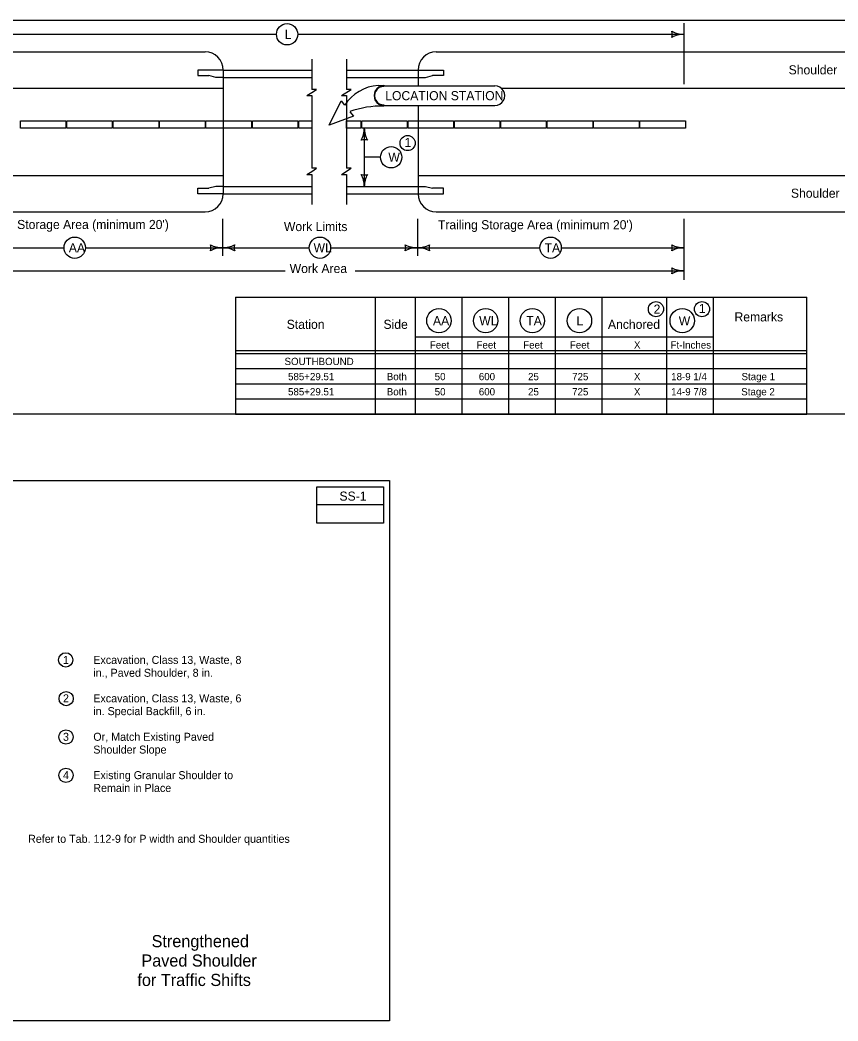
# Model space of a CAD drawing. Extents: x 8045 to 81668, y 6217 to 16762.
# Drawn here: x 8986 to 10335, y 10467 to 12118 of the extents above; entities that cross this region are included whole.
import ezdxf

# ---------------------------------------------------------------- set-up
doc = ezdxf.new("R2010")
doc.units = 0
for name, color, linetype in [('dsnNonPlotable', 7, 'Continuous'), ('dsnStdBlockModified', 7, 'Continuous'), ('dsnStdBlockNotModified', 7, 'Continuous'), ('dsnStdBorder', 7, 'Continuous'), ('dsnStdLineWork', 7, 'Continuous'), ('dsnStdNameDate', 7, 'Continuous'), ('Level 2', 7, 'Continuous'), ('Level 5', 7, 'Continuous')]:
    doc.layers.add(name, color=color, linetype=linetype)

msp = doc.modelspace()

# ---------------------------------------------------------------- linework, layer by layer
at = {"layer": 'dsnNonPlotable'}
for p, q in [((10080.5, 12113.1), (10080.5, 12012.3)), ((8530, 12094.5), (9408.5, 12094.5)), ((9443.8, 12094.5), (10080.5, 12094.5)), ((8162.3, 12065.5), (9290.8, 12065.5)), ((9672.2, 12065.5), (11020.7, 12065.5)), ((9466.8, 12053.5), (9466.8, 12003.7)), ((9523.9, 12053.5), (9523.9, 12003.7)), ((9320.8, 12035.5), (9278.8, 12035.5)), ((9278.8, 12035.5), (9278.8, 12026.5)), ((9278.8, 12026.5), (9296.8, 12026.5)), ((9308.8, 12023.5), (9296.8, 12026.5)), ((9320.8, 12023.5), (9308.8, 12023.5)), ((9320.8, 12035.5), (9320.8, 11831.5)), ((9320.8, 12035.5), (9466.8, 12035.5)), ((9320.8, 12023.5), (9466.8, 12023.5)), ((9523.9, 12035.5), (9642.2, 12035.5)), ((9523.9, 12023.5), (9642.2, 12023.5)), ((9642.2, 12035.5), (9684.2, 12035.5)), ((9642.2, 12035.5), (9642.2, 12009.5)), ((9642.2, 12023.5), (9654.2, 12023.5)), ((9654.2, 12023.5), (9666.2, 12026.5)), ((9684.2, 12026.5), (9666.2, 12026.5)), ((9684.2, 12035.5), (9684.2, 12026.5)), ((8078.7, 12005.5), (9320.8, 12005.5)), ((9576.3, 12010.1), (9585.8, 12010.4)), ((9585.8, 12010.4), (9585.8, 12008.6)), ((9585.8, 12009.5), (9769, 12009.5)), ((9779.7, 12005.5), (11111, 12005.5)), ((9458.8, 11993.6), (9466.8, 11998.6)), ((9458.8, 11993.6), (9466.8, 11993.6)), ((9466.8, 11998.6), (9474.8, 12003.7)), ((9474.8, 12003.7), (9466.8, 12003.7)), ((9466.8, 11993.6), (9466.8, 11933.5)), ((9515.9, 11993.6), (9531.9, 12003.7)), ((9515.9, 11993.6), (9523.9, 11993.6)), ((9531.9, 12003.7), (9523.9, 12003.7)), ((9523.9, 11993.6), (9523.9, 11933.5)), ((9495.4, 11944.5), (9515.5, 11984.5)), ((9515.5, 11984.5), (9521.1, 11977.5)), ((9585.8, 11977.9), (9585.8, 11976.1)), ((9585.8, 11977), (9769, 11977)), ((9642.2, 11977), (9642.2, 11831.5)), ((9535.6, 11959.5), (9495.4, 11944.5)), ((9529.7, 11966.8), (9535.6, 11959.5)), ((9553.5, 11939.8), (9553.5, 11843.5)), ((9466.8, 11933.5), (9466.8, 11873.5)), ((9523.9, 11933.5), (9523.9, 11873.5)), ((9580.1, 11891.7), (9553.5, 11891.7)), ((9466.8, 11868.4), (9474.8, 11873.5)), ((9474.8, 11873.5), (9466.8, 11873.5)), ((9515.9, 11863.4), (9531.9, 11873.5)), ((9531.9, 11873.5), (9523.9, 11873.5)), ((8078.7, 11861.5), (9320.8, 11861.5)), ((9458.8, 11863.4), (9466.8, 11868.4)), ((9458.8, 11863.4), (9466.8, 11863.4)), ((9466.8, 11863.4), (9466.8, 11813.5)), ((9515.9, 11863.4), (9523.9, 11863.4)), ((9523.9, 11863.4), (9523.9, 11813.5)), ((9642.2, 11861.5), (11111, 11861.5)), ((9278.8, 11840.5), (9296.8, 11840.5)), ((9278.8, 11831.5), (9278.8, 11840.5)), ((9308.8, 11843.5), (9296.8, 11840.5)), ((9320.8, 11843.5), (9308.8, 11843.5)), ((9320.8, 11843.5), (9466.8, 11843.5)), ((9523.9, 11843.5), (9642.2, 11843.5)), ((9642.2, 11843.5), (9654.2, 11843.5)), ((9654.2, 11843.5), (9666.2, 11840.5)), ((9684.2, 11840.5), (9666.2, 11840.5)), ((9684.2, 11831.5), (9684.2, 11840.5)), ((9320.8, 11831.5), (9278.8, 11831.5)), ((9320.8, 11831.5), (9466.8, 11831.5)), ((9523.9, 11831.5), (9642.2, 11831.5)), ((9642.2, 11831.5), (9684.2, 11831.5)), ((8162.3, 11801.5), (9290.8, 11801.5)), ((9319.6, 11790.2), (9319.6, 11729)), ((9641, 11790.2), (9641, 11729)), ((9672.2, 11801.5), (11020.7, 11801.5)), ((10080.5, 11790.2), (10080.5, 11689.4)), ((8832.1, 11742.4), (9058.2, 11742.4)), ((9093.5, 11742.4), (9319.6, 11742.4)), ((9319.6, 11742.4), (9462.8, 11742.4)), ((9497.8, 11742.4), (9641, 11742.4)), ((9510.5, 11742.4), (9641, 11742.4)), ((9641, 11742.4), (9843.1, 11742.4)), ((9878.4, 11742.4), (10080.5, 11742.4)), ((8832.1, 11704.5), (9422.9, 11704.5)), ((9538.2, 11704.5), (10080.5, 11704.5)), ((9539.6, 11704.5), (9641, 11704.5)), ((9572.1, 11468.1), (9572.1, 11661.1)), ((9638.1, 11468.1), (9638.1, 11661.1)), ((9715.1, 11468.1), (9715.1, 11661.1)), ((9792.1, 11468.1), (9792.1, 11661.1)), ((9869.1, 11468.1), (9869.1, 11661.1)), ((9638.1, 11595.3), (10129.7, 11595.3)), ((9341.1, 11573.1), (10283.7, 11573.1)), ((9341.1, 11568.1), (10283.7, 11568.1))]:
    msp.add_line(p, q, dxfattribs=at)
for points in [[(8986.3, 11951.8), (9061.3, 11951.8), (9061.3, 11939.8), (8986.3, 11939.8)], [(9062.8, 11951.8), (9137.8, 11951.8), (9137.8, 11939.8), (9062.8, 11939.8)], [(9139.3, 11951.8), (9214.3, 11951.8), (9214.3, 11939.8), (9139.3, 11939.8)], [(9215.8, 11951.8), (9290.8, 11951.8), (9290.8, 11939.8), (9215.8, 11939.8)], [(9292.3, 11951.8), (9367.3, 11951.8), (9367.3, 11939.8), (9292.3, 11939.8)], [(9368.8, 11951.8), (9443.8, 11951.8), (9443.8, 11939.8), (9368.8, 11939.8)], [(9549.2, 11951.8), (9624.2, 11951.8), (9624.2, 11939.8), (9549.2, 11939.8)], [(9625.7, 11951.8), (9700.7, 11951.8), (9700.7, 11939.8), (9625.7, 11939.8)], [(9702.2, 11951.8), (9777.2, 11951.8), (9777.2, 11939.8), (9702.2, 11939.8)], [(9778.7, 11951.8), (9853.7, 11951.8), (9853.7, 11939.8), (9778.7, 11939.8)], [(9855.2, 11951.8), (9930.2, 11951.8), (9930.2, 11939.8), (9855.2, 11939.8)], [(9931.7, 11951.8), (10006.7, 11951.8), (10006.7, 11939.8), (9931.7, 11939.8)], [(10008.2, 11951.8), (10083.2, 11951.8), (10083.2, 11939.8), (10008.2, 11939.8)]]:
    msp.add_lwpolyline(points, close=True, dxfattribs=at)
for points in [[(9466.8, 11939.8), (9445.3, 11939.8), (9445.3, 11951.8), (9466.8, 11951.8)], [(9466.8, 11951.8), (9466.8, 11939.8)], [(9523.9, 11939.8), (9523.9, 11951.8)], [(9523.9, 11951.8), (9547.7, 11951.8), (9547.7, 11939.8), (9523.9, 11939.8)]]:
    msp.add_lwpolyline(points, dxfattribs=at)
for centre, radius in [((9426.2, 12094.5), 17.6), ((9624.9, 11915.1), 12.5), ((9597.8, 11891.7), 17.6), ((9075.9, 11742.4), 17.6), ((9480.3, 11742.4), 17.6), ((9860.8, 11742.4), 17.6), ((9676.6, 11622.1), 20.1), ((9753.6, 11622.1), 20.1), ((9830.6, 11622.1), 20.1), ((9908.4, 11622.1), 20.1), ((10034.6, 11641.2), 12.5), ((10077.9, 11622.1), 20.1), ((10110.5, 11641.2), 12.5)]:
    msp.add_circle(centre, radius, dxfattribs=at)
for centre, radius, start, end in [((10044.9, 12094.5), 16.4, 342.2666, 17.7333), ((10080.5, 12137), 42.5, 241.9275, 270), ((10080.5, 12052), 42.5, 90, 118.0725), ((9290.8, 12035.5), 30, 0, 90), ((9672.2, 12035.5), 30, 90, 180), ((9511, 11939.8), 42.5, 331.9275, 0), ((9596, 11939.8), 42.5, 180, 208.0725), ((9553.5, 11904.2), 16.4, 72.2666, 107.7334), ((9553.5, 11879.1), 16.4, 252.2666, 287.7334), ((9511, 11843.5), 42.5, 0, 28.0725), ((9596, 11843.5), 42.5, 151.9275, 180), ((9290.8, 11831.5), 30, 270, 360), ((9672.2, 11831.5), 30, 180, 270), ((9284, 11742.4), 16.4, 342.2666, 17.7333), ((9319.6, 11784.9), 42.5, 241.9275, 270), ((9319.6, 11699.9), 42.5, 90, 118.0725), ((9319.6, 11784.9), 42.5, 270, 298.0725), ((9319.6, 11699.9), 42.5, 61.9275, 90), ((9355.3, 11742.4), 16.4, 162.2666, 197.7334), ((9605.4, 11742.4), 16.4, 342.2666, 17.7333), ((9641, 11784.9), 42.5, 241.9275, 270), ((9641, 11699.9), 42.5, 90, 118.0725), ((9641, 11784.9), 42.5, 270, 298.0725), ((9641, 11699.9), 42.5, 61.9275, 90), ((9676.7, 11742.4), 16.4, 162.2666, 197.7334), ((10044.9, 11742.4), 16.4, 342.2666, 17.7333), ((10080.5, 11784.9), 42.5, 241.9275, 270), ((10080.5, 11699.9), 42.5, 90, 118.0725), ((10044.9, 11704.5), 16.4, 342.2666, 17.7333), ((10080.5, 11747), 42.5, 241.9275, 270), ((10080.5, 11662), 42.5, 90, 118.0725)]:
    msp.add_arc(centre, radius, start, end, dxfattribs=at)
for centre, major_axis, start_param, end_param in [((9580.9, 11939.8), (-70.8, 0), 4.776871, 5.71778), ((9585.8, 11993.3), (-16.3, 0), 4.712389, 7.853982), ((9585.8, 11993.3), (15.4, 0), 1.570796, 4.712389), ((9769, 11993.3), (16.3, 0), 4.712389, 7.853982), ((9583, 11820.1), (-156.9, 0), 4.694293, 5.059134)]:
    msp.add_ellipse(centre, major_axis=major_axis, ratio=0.995025, start_param=start_param, end_param=end_param, dxfattribs=at)
at = {"layer": 'dsnStdBlockModified'}
msp.add_line((8047, 12118.1), (11152, 12118.1), dxfattribs=at)
at = {"layer": 'dsnStdBlockNotModified'}
for p, q in [((9341.1, 11543.1), (10283.7, 11543.1)), ((9341.1, 11518.1), (10283.7, 11518.1)), ((9341.1, 11493.1), (10283.7, 11493.1)), ((9341.1, 11468.1), (10283.7, 11468.1))]:
    msp.add_line(p, q, dxfattribs=at)
at = {"layer": 'dsnStdBorder'}
msp.add_line((11152, 11468.1), (8047, 11468.1), dxfattribs=at)
at = {"layer": 'dsnStdLineWork'}
for centre in [(9061, 11062.5), (9061.7, 10998.7), (9061.4, 10935.4), (9061.4, 10872.2)]:
    msp.add_circle(centre, 11.8, dxfattribs=at)
at = {"layer": 'dsnStdNameDate'}
msp.add_lwpolyline([(8044.5, 11358.2), (9595.3, 11358.2), (9595.3, 10466.9), (8044.5, 10466.9)], close=True, dxfattribs=at)
msp.add_lwpolyline([(9585.3, 11348.2), (9585.3, 11288.2), (9475.3, 11288.2), (9475.3, 11348.2), (9585.3, 11348.2), (9585.3, 11318.2), (9475.3, 11318.2)], dxfattribs=at)
at = {"layer": 'Level 2'}
for p, q in [((9341.1, 11661.1), (9341.1, 11468.1)), ((9341.1, 11661.1), (10283.7, 11661.1)), ((9946.1, 11468.1), (9946.1, 11661.1)), ((10052.7, 11468.1), (10052.7, 11661.1)), ((10129.7, 11468.1), (10129.7, 11661.1)), ((10283.7, 11468.1), (10283.7, 11661.1))]:
    msp.add_line(p, q, dxfattribs=at)

# ---------------------------------------------------------------- texts
at = {"layer": 'dsnStdLineWork'}
for s, height, p in [('SS-1', 15, (9512.5, 11325.2)), ('1', 13.2, (9056.5, 11055.9)), ('Excavation, Class 13, Waste, 8 ', 13.2, (9106.5, 11055.9)), ('in., Paved Shoulder, 8 in.', 13.2, (9106.5, 11034.7)), ('2', 13.2, (9056.5, 10992.5)), ('Excavation, Class 13, Waste, 6 ', 13.2, (9106.5, 10992.5)), ('in. Special Backfill, 6 in.', 13.2, (9106.5, 10971.4)), ('3', 13.2, (9056.5, 10929.1)), ('Or, Match Existing Paved ', 13.2, (9106.5, 10929.1)), ('Shoulder Slope', 13.2, (9106.5, 10908)), ('4', 13.2, (9056.5, 10865.8)), ('Existing Granular Shoulder to ', 13.2, (9106.5, 10865.8)), ('Remain in Place', 13.2, (9106.5, 10844.7)), ('Refer to Tab. 112-9 for P width and Shoulder quantities', 13.2, (8998.9, 10760.8)), ('Strengthened ', 20, (9202.6, 10588.6)), ('Paved Shoulder', 20, (9185.8, 10556.6)), ('for Traffic Shifts', 20, (9179.2, 10524.6))]:
    msp.add_text(s, height=height, dxfattribs=at).set_placement(p)
at = {"layer": 'Level 5'}
for s, height, p in [('L', 15, (9422.2, 12087)), ('Shoulder', 15, (10253.4, 12028.4)), ('LOCATION STATION', 15, (9588, 11985.8)), ('1', 15, (9619.7, 11908.5)), ('W', 15, (9593.2, 11884.2)), ('Shoulder', 15, (10257.2, 11824.9)), ("Approach Storage Area (minimum 20')", 15, (8889.4, 11773.3)), ('Work Limits', 15, (9420.9, 11769.9)), ("Trailing Storage Area (minimum 20')", 15, (9674.9, 11772.9)), ('AA', 15, (9066.1, 11734.9)), ('WL', 15, (9469.8, 11734.9)), ('TA', 15, (9850.9, 11734.9)), ('Work Area', 15, (9430.4, 11700.7)), ('2', 15, (10030.7, 11633.7)), ('1', 15, (10105.3, 11634.7)), ('Station', 15, (9425.5, 11608.6)), ('Side', 15, (9585.1, 11608.6)), ('AA', 15, (9666.8, 11614.6)), ('WL', 15, (9743.1, 11614.6)), ('TA', 15, (9820.7, 11614.6)), ('L', 15, (9903.5, 11614.2)), ('Anchored', 15, (9955.4, 11608.6)), ('W', 15, (10072.2, 11614.2)), ('Remarks', 15, (10164.1, 11620.9)), ('Feet', 12, (9661.6, 11576.1)), ('Feet', 12, (9738.6, 11576.1)), ('Feet', 12, (9815.6, 11576.1)), ('Feet', 12, (9892.6, 11576.1)), ('X', 12, (9998.3, 11576.1)), ('Ft-Inches', 12, (10058.6, 11576.1)), ('SOUTHBOUND', 12, (9421.9, 11548.9)), ('585+29.51', 12, (9427.7, 11523.9)), ('Both', 12, (9590.6, 11523.9)), ('50', 12, (9669.6, 11523.9)), ('600', 12, (9742.4, 11523.9)), ('25', 12, (9823.6, 11523.9)), ('725', 12, (9896.3, 11523.9)), ('X', 12, (9998.3, 11523.9)), ('18-9 1/4', 12, (10059.7, 11523.9)), ('Stage 1', 12, (10175.7, 11523.9)), ('585+29.51', 12, (9427.7, 11498.9)), ('Both', 12, (9590.6, 11498.9)), ('50', 12, (9669.6, 11498.9)), ('600', 12, (9742.4, 11498.9)), ('25', 12, (9823.6, 11498.9)), ('725', 12, (9896.3, 11498.9)), ('X', 12, (9998.3, 11498.9)), ('14-9 7/8', 12, (10059.7, 11498.9)), ('Stage 2', 12, (10175.3, 11498.9))]:
    msp.add_text(s, height=height, dxfattribs=at).set_placement(p)

doc.saveas('drawing.dxf')
